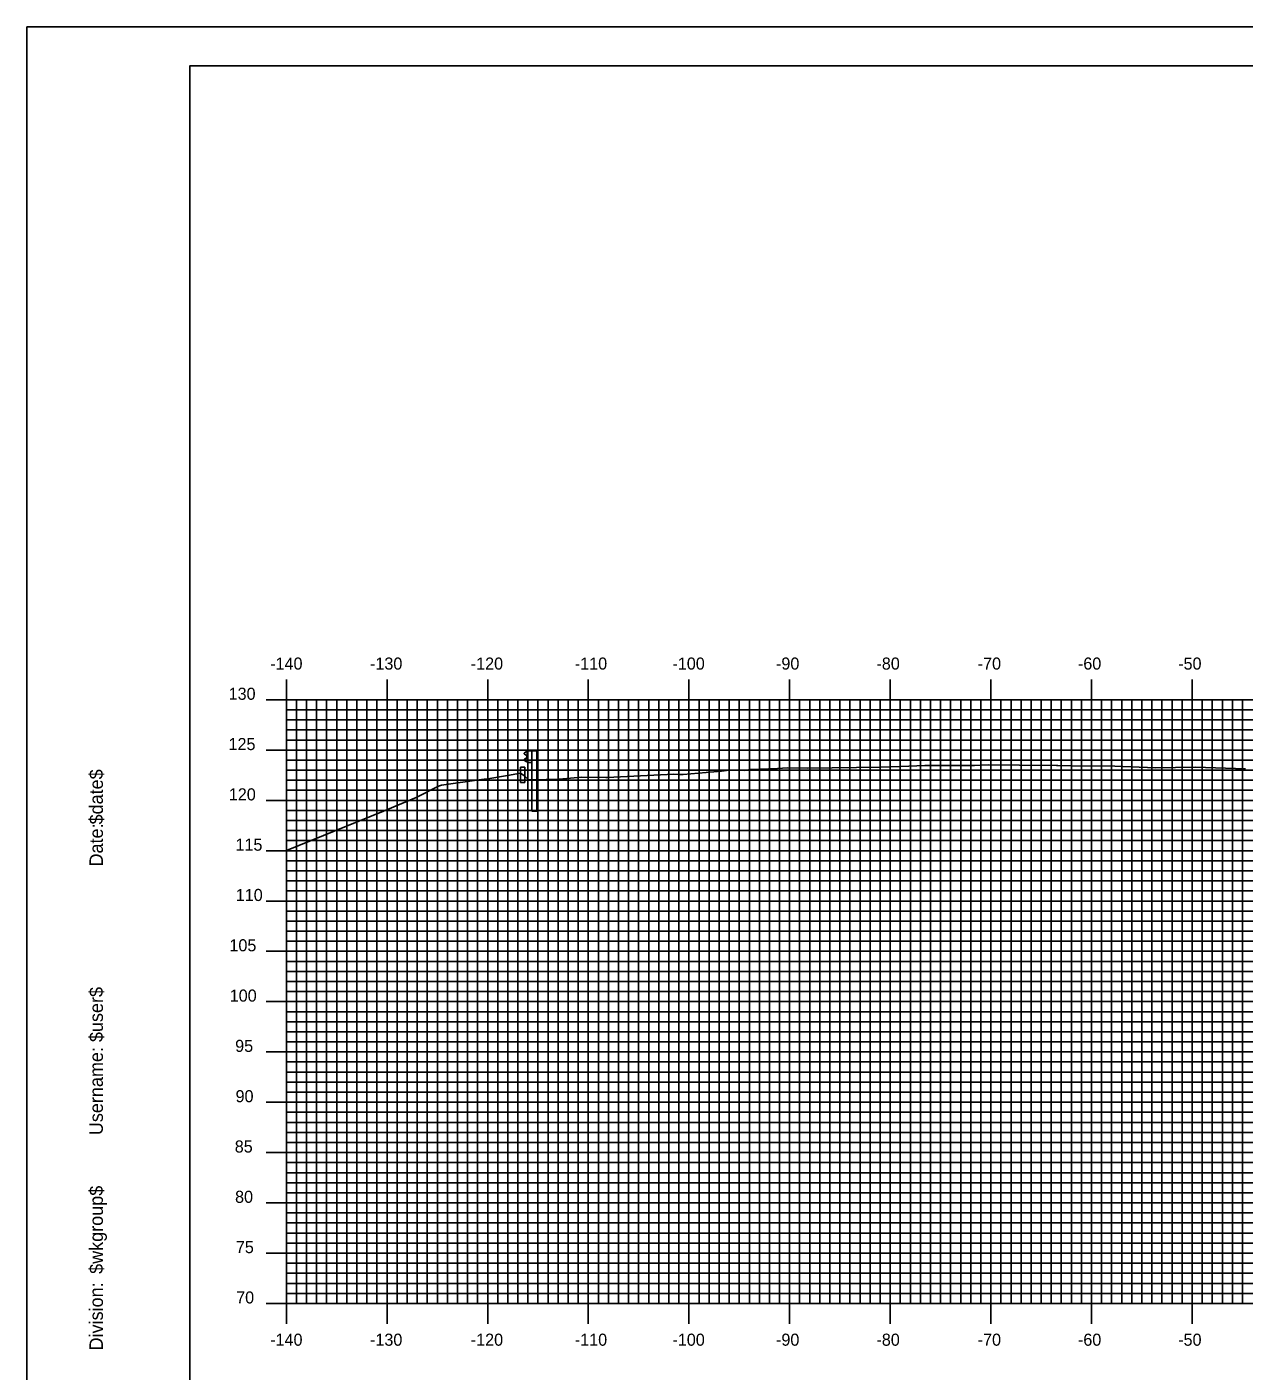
# Model space of a CAD drawing. Extents: x 856871 to 857214, y 364366 to 364586.
# Drawn here: x 856871 to 856992, y 364452.1 to 364585.7 of the extents above; entities that cross this region are included whole.
import ezdxf

# ---------------------------------------------------------------- set-up
doc = ezdxf.new("R2010")
doc.units = 0
for name, color, linetype in [('BORDER', 7, 'Continuous'), ('H_V ANNOTATION', 7, 'Continuous'), ('M_Roadway_Centerline', 7, 'Continuous'), ('MAJOR', 7, 'Continuous'), ('MINOR', 7, 'Continuous'), ('PLOT BOUNDARY', 7, 'Continuous'), ('S_Curb_Type_1', 7, 'Continuous'), ('S_Guardrail_Beam', 7, 'Continuous'), ('S_Roadway_Centerline', 7, 'Continuous')]:
    doc.layers.add(name, color=color, linetype=linetype)

msp = doc.modelspace()

# ---------------------------------------------------------------- linework, layer by layer
at = {"layer": 'BORDER'}
msp.add_lwpolyline([(856887.22, 364371.79), (857207.22, 364371.79), (857207.22, 364581.79), (856887.22, 364581.79)], close=True, dxfattribs=at)
at = {"layer": 'MAJOR'}
for p, q in [((856896.82, 364520.79), (856896.82, 364518.79)), ((856906.82, 364520.79), (856906.82, 364518.79)), ((856916.82, 364520.79), (856916.82, 364518.79)), ((856926.82, 364520.79), (856926.82, 364518.79)), ((856936.82, 364520.79), (856936.82, 364518.79)), ((856946.82, 364520.79), (856946.82, 364518.79)), ((856956.82, 364520.79), (856956.82, 364518.79)), ((856966.82, 364520.79), (856966.82, 364518.79)), ((856976.82, 364520.79), (856976.82, 364518.79)), ((856986.82, 364520.79), (856986.82, 364518.79)), ((856894.82, 364518.79), (856896.82, 364518.79)), ((856896.82, 364518.79), (857176.82, 364518.79)), ((856896.82, 364458.79), (856896.82, 364518.79)), ((856896.82, 364458.79), (856896.82, 364518.79)), ((856896.82, 364518.79), (857176.82, 364518.79)), ((856906.82, 364458.79), (856906.82, 364518.79)), ((856916.82, 364458.79), (856916.82, 364518.79)), ((856926.82, 364458.79), (856926.82, 364518.79)), ((856936.82, 364458.79), (856936.82, 364518.79)), ((856946.82, 364458.79), (856946.82, 364518.79)), ((856956.82, 364458.79), (856956.82, 364518.79)), ((856966.82, 364458.79), (856966.82, 364518.79)), ((856976.82, 364458.79), (856976.82, 364518.79)), ((856986.82, 364458.79), (856986.82, 364518.79)), ((856894.82, 364513.79), (856896.82, 364513.79)), ((856896.82, 364513.79), (857176.82, 364513.79)), ((856894.82, 364508.79), (856896.82, 364508.79)), ((856896.82, 364508.79), (857176.82, 364508.79)), ((856894.82, 364503.79), (856896.82, 364503.79)), ((856896.82, 364503.79), (857176.82, 364503.79)), ((856894.82, 364498.79), (856896.82, 364498.79)), ((856896.82, 364498.79), (857176.82, 364498.79)), ((856894.82, 364493.79), (856896.82, 364493.79)), ((856896.82, 364493.79), (857176.82, 364493.79)), ((856894.82, 364488.79), (856896.82, 364488.79)), ((856896.82, 364488.79), (857176.82, 364488.79)), ((856894.82, 364483.79), (856896.82, 364483.79)), ((856896.82, 364483.79), (857176.82, 364483.79)), ((856894.82, 364478.79), (856896.82, 364478.79)), ((856896.82, 364478.79), (857176.82, 364478.79)), ((856894.82, 364473.79), (856896.82, 364473.79)), ((856896.82, 364473.79), (857176.82, 364473.79)), ((856894.82, 364468.79), (856896.82, 364468.79)), ((856896.82, 364468.79), (857176.82, 364468.79)), ((856894.82, 364463.79), (856896.82, 364463.79)), ((856896.82, 364463.79), (857176.82, 364463.79)), ((856894.82, 364458.79), (856896.82, 364458.79)), ((856896.82, 364458.79), (857176.82, 364458.79)), ((856896.82, 364458.79), (857176.82, 364458.79)), ((856896.82, 364456.78), (856896.82, 364458.79)), ((856906.82, 364456.78), (856906.82, 364458.79)), ((856916.82, 364456.78), (856916.82, 364458.79)), ((856926.82, 364456.78), (856926.82, 364458.79)), ((856936.82, 364456.78), (856936.82, 364458.79)), ((856946.82, 364456.78), (856946.82, 364458.79)), ((856956.82, 364456.78), (856956.82, 364458.79)), ((856966.82, 364456.78), (856966.82, 364458.79)), ((856976.82, 364456.78), (856976.82, 364458.79)), ((856986.82, 364456.78), (856986.82, 364458.79))]:
    msp.add_line(p, q, dxfattribs=at)
at = {"layer": 'MINOR'}
for p, q in [((856897.82, 364458.79), (856897.82, 364518.79)), ((856898.82, 364458.79), (856898.82, 364518.79)), ((856899.82, 364458.79), (856899.82, 364518.79)), ((856900.82, 364458.79), (856900.82, 364518.79)), ((856901.82, 364458.79), (856901.82, 364518.79)), ((856902.82, 364458.79), (856902.82, 364518.79)), ((856903.82, 364458.79), (856903.82, 364518.79)), ((856904.82, 364458.79), (856904.82, 364518.79)), ((856905.82, 364458.79), (856905.82, 364518.79)), ((856907.82, 364458.79), (856907.82, 364518.79)), ((856908.82, 364458.79), (856908.82, 364518.79)), ((856909.82, 364458.79), (856909.82, 364518.79)), ((856910.82, 364458.79), (856910.82, 364518.79)), ((856911.82, 364458.79), (856911.82, 364518.79)), ((856912.82, 364458.79), (856912.82, 364518.79)), ((856913.82, 364458.79), (856913.82, 364518.79)), ((856914.82, 364458.79), (856914.82, 364518.79)), ((856915.82, 364458.79), (856915.82, 364518.79)), ((856917.82, 364458.79), (856917.82, 364518.79)), ((856918.82, 364458.79), (856918.82, 364518.79)), ((856919.82, 364458.79), (856919.82, 364518.79)), ((856920.82, 364458.79), (856920.82, 364518.79)), ((856921.82, 364458.79), (856921.82, 364518.79)), ((856922.82, 364458.79), (856922.82, 364518.79)), ((856923.82, 364458.79), (856923.82, 364518.79)), ((856924.82, 364458.79), (856924.82, 364518.79)), ((856925.82, 364458.79), (856925.82, 364518.79)), ((856927.82, 364458.79), (856927.82, 364518.79)), ((856928.82, 364458.79), (856928.82, 364518.79)), ((856929.82, 364458.79), (856929.82, 364518.79)), ((856930.82, 364458.79), (856930.82, 364518.79)), ((856931.82, 364458.79), (856931.82, 364518.79)), ((856932.82, 364458.79), (856932.82, 364518.79)), ((856933.82, 364458.79), (856933.82, 364518.79)), ((856934.82, 364458.79), (856934.82, 364518.79)), ((856935.82, 364458.79), (856935.82, 364518.79)), ((856937.82, 364458.79), (856937.82, 364518.79)), ((856938.82, 364458.79), (856938.82, 364518.79)), ((856939.82, 364458.79), (856939.82, 364518.79)), ((856940.82, 364458.79), (856940.82, 364518.79)), ((856941.82, 364458.79), (856941.82, 364518.79)), ((856942.82, 364458.79), (856942.82, 364518.79)), ((856943.82, 364458.79), (856943.82, 364518.79)), ((856944.82, 364458.79), (856944.82, 364518.79)), ((856945.82, 364458.79), (856945.82, 364518.79)), ((856947.82, 364458.79), (856947.82, 364518.79)), ((856948.82, 364458.79), (856948.82, 364518.79)), ((856949.82, 364458.79), (856949.82, 364518.79)), ((856950.82, 364458.79), (856950.82, 364518.79)), ((856951.82, 364458.79), (856951.82, 364518.79)), ((856952.82, 364458.79), (856952.82, 364518.79)), ((856953.82, 364458.79), (856953.82, 364518.79)), ((856954.82, 364458.79), (856954.82, 364518.79)), ((856955.82, 364458.79), (856955.82, 364518.79)), ((856957.82, 364458.79), (856957.82, 364518.79)), ((856958.82, 364458.79), (856958.82, 364518.79)), ((856959.82, 364458.79), (856959.82, 364518.79)), ((856960.82, 364458.79), (856960.82, 364518.79)), ((856961.82, 364458.79), (856961.82, 364518.79)), ((856962.82, 364458.79), (856962.82, 364518.79)), ((856963.82, 364458.79), (856963.82, 364518.79)), ((856964.82, 364458.79), (856964.82, 364518.79)), ((856965.82, 364458.79), (856965.82, 364518.79)), ((856967.82, 364458.79), (856967.82, 364518.79)), ((856968.82, 364458.79), (856968.82, 364518.79)), ((856969.82, 364458.79), (856969.82, 364518.79)), ((856970.82, 364458.79), (856970.82, 364518.79)), ((856971.82, 364458.79), (856971.82, 364518.79)), ((856972.82, 364458.79), (856972.82, 364518.79)), ((856973.82, 364458.79), (856973.82, 364518.79)), ((856974.82, 364458.79), (856974.82, 364518.79)), ((856975.82, 364458.79), (856975.82, 364518.79)), ((856977.82, 364458.79), (856977.82, 364518.79)), ((856978.82, 364458.79), (856978.82, 364518.79)), ((856979.82, 364458.79), (856979.82, 364518.79)), ((856980.82, 364458.79), (856980.82, 364518.79)), ((856981.82, 364458.79), (856981.82, 364518.79)), ((856982.82, 364458.79), (856982.82, 364518.79)), ((856983.82, 364458.79), (856983.82, 364518.79)), ((856984.82, 364458.79), (856984.82, 364518.79)), ((856985.82, 364458.79), (856985.82, 364518.79)), ((856987.82, 364458.79), (856987.82, 364518.79)), ((856988.82, 364458.79), (856988.82, 364518.79)), ((856989.82, 364458.79), (856989.82, 364518.79)), ((856990.82, 364458.79), (856990.82, 364518.79)), ((856991.82, 364458.79), (856991.82, 364518.79)), ((856896.82, 364517.79), (857176.82, 364517.79)), ((856896.82, 364517.79), (856898.83, 364517.79)), ((856896.82, 364516.79), (857176.82, 364516.79)), ((856896.82, 364516.79), (856898.83, 364516.79)), ((856896.82, 364515.79), (857176.82, 364515.79)), ((856896.82, 364515.79), (856898.83, 364515.79)), ((856896.82, 364514.79), (857176.82, 364514.79)), ((856896.82, 364514.79), (856898.83, 364514.79)), ((856896.82, 364512.79), (857176.82, 364512.79)), ((856896.82, 364512.79), (856898.83, 364512.79)), ((856896.82, 364511.79), (857176.82, 364511.79)), ((856896.82, 364511.79), (856898.83, 364511.79)), ((856896.82, 364510.79), (857176.82, 364510.79)), ((856896.82, 364510.79), (856898.83, 364510.79)), ((856896.82, 364509.79), (857176.82, 364509.79)), ((856896.82, 364509.79), (856898.83, 364509.79)), ((856896.82, 364507.79), (857176.82, 364507.79)), ((856896.82, 364507.79), (856898.83, 364507.79)), ((856896.82, 364506.79), (857176.82, 364506.79)), ((856896.82, 364506.79), (856898.83, 364506.79)), ((856896.82, 364505.79), (857176.82, 364505.79)), ((856896.82, 364505.79), (856898.83, 364505.79)), ((856896.82, 364504.79), (857176.82, 364504.79)), ((856896.82, 364504.79), (856898.83, 364504.79)), ((856896.82, 364502.79), (857176.82, 364502.79)), ((856896.82, 364502.79), (856898.83, 364502.79)), ((856896.82, 364501.79), (857176.82, 364501.79)), ((856896.82, 364501.79), (856898.83, 364501.79)), ((856896.82, 364500.79), (857176.82, 364500.79)), ((856896.82, 364500.79), (856898.83, 364500.79)), ((856896.82, 364499.79), (857176.82, 364499.79)), ((856896.82, 364499.79), (856898.83, 364499.79)), ((856896.82, 364497.79), (857176.82, 364497.79)), ((856896.82, 364497.79), (856898.83, 364497.79)), ((856896.82, 364496.79), (857176.82, 364496.79)), ((856896.82, 364496.79), (856898.83, 364496.79)), ((856896.82, 364495.79), (857176.82, 364495.79)), ((856896.82, 364495.79), (856898.83, 364495.79)), ((856896.82, 364494.79), (857176.82, 364494.79)), ((856896.82, 364494.79), (856898.83, 364494.79)), ((856896.82, 364492.79), (857176.82, 364492.79)), ((856896.82, 364492.79), (856898.83, 364492.79)), ((856896.82, 364491.79), (857176.82, 364491.79)), ((856896.82, 364491.79), (856898.83, 364491.79)), ((856896.82, 364490.79), (857176.82, 364490.79)), ((856896.82, 364490.79), (856898.83, 364490.79)), ((856896.82, 364489.79), (857176.82, 364489.79)), ((856896.82, 364489.79), (856898.83, 364489.79)), ((856896.82, 364487.79), (857176.82, 364487.79)), ((856896.82, 364487.79), (856898.83, 364487.79)), ((856896.82, 364486.79), (857176.82, 364486.79)), ((856896.82, 364486.79), (856898.83, 364486.79)), ((856896.82, 364485.79), (857176.82, 364485.79)), ((856896.82, 364485.79), (856898.83, 364485.79)), ((856896.82, 364484.79), (857176.82, 364484.79)), ((856896.82, 364484.79), (856898.83, 364484.79)), ((856896.82, 364482.79), (857176.82, 364482.79)), ((856896.82, 364482.79), (856898.83, 364482.79)), ((856896.82, 364481.79), (857176.82, 364481.79)), ((856896.82, 364481.79), (856898.83, 364481.79)), ((856896.82, 364480.79), (857176.82, 364480.79)), ((856896.82, 364480.79), (856898.83, 364480.79)), ((856896.82, 364479.79), (857176.82, 364479.79)), ((856896.82, 364479.79), (856898.83, 364479.79)), ((856896.82, 364477.79), (857176.82, 364477.79)), ((856896.82, 364477.79), (856898.83, 364477.79)), ((856896.82, 364476.79), (857176.82, 364476.79)), ((856896.82, 364476.79), (856898.83, 364476.79)), ((856896.82, 364475.79), (857176.82, 364475.79)), ((856896.82, 364475.79), (856898.83, 364475.79)), ((856896.82, 364474.79), (857176.82, 364474.79)), ((856896.82, 364474.79), (856898.83, 364474.79)), ((856896.82, 364472.79), (857176.82, 364472.79)), ((856896.82, 364472.79), (856898.83, 364472.79)), ((856896.82, 364471.79), (857176.82, 364471.79)), ((856896.82, 364471.79), (856898.83, 364471.79)), ((856896.82, 364470.79), (857176.82, 364470.79)), ((856896.82, 364470.79), (856898.83, 364470.79)), ((856896.82, 364469.79), (857176.82, 364469.79)), ((856896.82, 364469.79), (856898.83, 364469.79)), ((856896.82, 364467.79), (857176.82, 364467.79)), ((856896.82, 364467.79), (856898.83, 364467.79)), ((856896.82, 364466.79), (857176.82, 364466.79)), ((856896.82, 364466.79), (856898.83, 364466.79)), ((856896.82, 364465.79), (857176.82, 364465.79)), ((856896.82, 364465.79), (856898.83, 364465.79)), ((856896.82, 364464.79), (857176.82, 364464.79)), ((856896.82, 364464.79), (856898.83, 364464.79)), ((856896.82, 364462.79), (857176.82, 364462.79)), ((856896.82, 364462.79), (856898.83, 364462.79)), ((856896.82, 364461.79), (857176.82, 364461.79)), ((856896.82, 364461.79), (856898.83, 364461.79)), ((856896.82, 364460.79), (857176.82, 364460.79)), ((856896.82, 364460.79), (856898.83, 364460.79)), ((856896.82, 364459.79), (857176.82, 364459.79)), ((856896.82, 364459.79), (856898.83, 364459.79))]:
    msp.add_line(p, q, dxfattribs=at)
at = {"layer": 'PLOT BOUNDARY'}
msp.add_lwpolyline([(856871.04, 364365.67), (857211.04, 364365.67), (857211.04, 364585.67), (856871.04, 364585.67)], close=True, dxfattribs=at)
at = {"layer": 'S_Curb_Type_1'}
msp.add_lwpolyline([(856920.09, 364512.08), (856920.51, 364512.08), (856920.51, 364510.58), (856920.09, 364510.58)], close=True, dxfattribs=at)
msp.add_lwpolyline([(856920.09, 364512.08), (856920.51, 364512.08), (856920.51, 364510.58), (856920.09, 364510.58)], close=True, dxfattribs=at)
at = {"layer": 'S_Guardrail_Beam'}
for p, q in [((856920.63, 364513.62), (856920.49, 364513.52)), ((856920.63, 364513.62), (856920.49, 364513.52)), ((856920.49, 364513.38), (856920.68, 364513.24)), ((856920.49, 364513.38), (856920.68, 364513.24)), ((856920.73, 364513.64), (856920.65, 364513.63)), ((856920.73, 364513.64), (856920.65, 364513.63)), ((856920.73, 364513.72), (856921.22, 364513.72)), ((856920.73, 364512.55), (856920.73, 364513.72)), ((856920.73, 364513.72), (856921.22, 364513.72)), ((856920.73, 364512.55), (856920.73, 364513.72)), ((856921.22, 364513.72), (856921.71, 364513.72)), ((856921.22, 364513.72), (856921.22, 364512.55)), ((856921.22, 364513.72), (856921.71, 364513.72)), ((856921.22, 364513.72), (856921.22, 364512.55)), ((856921.71, 364513.72), (856921.71, 364507.72)), ((856921.71, 364513.72), (856921.71, 364507.72)), ((856920.68, 364513.02), (856920.49, 364512.89)), ((856920.68, 364513.02), (856920.49, 364512.89)), ((856920.49, 364512.74), (856920.63, 364512.64)), ((856920.49, 364512.74), (856920.63, 364512.64)), ((856920.65, 364512.64), (856920.73, 364512.62)), ((856920.65, 364512.64), (856920.73, 364512.62)), ((856920.72, 364513.18), (856920.72, 364513.09)), ((856920.72, 364513.18), (856920.72, 364513.09)), ((856921.22, 364512.55), (856920.73, 364512.55)), ((856921.22, 364512.55), (856920.73, 364512.55)), ((856921.22, 364507.72), (856921.22, 364512.55)), ((856921.22, 364507.72), (856921.22, 364512.55)), ((856921.22, 364507.72), (856921.71, 364507.72)), ((856921.22, 364507.72), (856921.71, 364507.72))]:
    msp.add_line(p, q, dxfattribs=at)
for centre, major_axis, start_param, end_param in [((856920.54, 364513.45), (-0.0877, 0), 5.323254, 7.243116), ((856920.54, 364513.45), (-0.0877, 0), 5.323254, 7.243116), ((856920.66, 364513.59), (-0.0417, 0), 4.886922, 5.323254), ((856920.66, 364513.59), (-0.0417, 0), 4.886922, 5.323254), ((856920.54, 364512.82), (-0.0877, 0), 5.323254, 7.243116), ((856920.54, 364512.82), (-0.0877, 0), 5.323254, 7.243116), ((856920.66, 364512.68), (-0.0417, 0), 0.959931, 1.396263), ((856920.66, 364512.68), (-0.0417, 0), 0.959931, 1.396263), ((856920.64, 364513.18), (0.0789, 0), 0, 0.959931), ((856920.64, 364513.18), (0.0789, 0), 0, 0.959931), ((856920.64, 364513.09), (0.0789, 0), 5.323254, 6.283185), ((856920.64, 364513.09), (0.0789, 0), 5.323254, 6.283185)]:
    msp.add_ellipse(centre, major_axis=major_axis, ratio=0.995501, start_param=start_param, end_param=end_param, dxfattribs=at)
at = {"layer": 'S_Roadway_Centerline'}
msp.add_lwpolyline([(856896.82, 364503.81), (856906.48, 364507.73), (856909.73, 364509.09), (856911.94, 364510.2), (856912.23, 364510.32), (856916.2, 364510.86), (856917.04, 364510.98), (856918.79, 364511.28), (856920.09, 364511.5), (856920.52, 364511.2), (856920.86, 364510.88), (856921.35, 364510.82), (856923.94, 364510.91), (856926.16, 364511.1), (856928.56, 364511.06), (856928.7, 364511.06), (856935.31, 364511.39), (856935.9, 364511.37), (856936.23, 364511.37), (856940.06, 364511.71), (856940.82, 364511.78), (856942.3, 364511.75), (856942.93, 364511.87), (856945.61, 364511.97), (856946.62, 364512.01), (856948.64, 364512), (856955.89, 364512.09), (856958.67, 364512.2), (856960.26, 364512.27), (856963.05, 364512.25), (856965.2, 364512.25), (856965.78, 364512.29), (856966.62, 364512.34), (856969.65, 364512.29), (856973.34, 364512.25), (856973.48, 364512.25), (856974.88, 364512.21), (856979.12, 364512.2), (856983.19, 364512.02), (856987.16, 364512.08), (856992.11, 364511.94)], dxfattribs=at)

# ---------------------------------------------------------------- texts
at = {"layer": 'BORDER'}
for s, p in [('$date$', (856878.59, 364506.4)), ('Date:', (856878.59, 364502.22)), ('$user$', (856878.59, 364484.77)), ('Username:', (856878.59, 364475.52)), ('$wkgroup$', (856878.59, 364461.73)), ('Division:', (856878.59, 364454.12))]:
    msp.add_text(s, height=1.339, rotation=90, dxfattribs=at).set_placement(p)
at = {"layer": 'H_V ANNOTATION'}
for s, p in [('-140', (856895.21, 364521.79)), ('-130', (856905.13, 364521.79)), ('-120', (856915.14, 364521.79)), ('-110', (856925.48, 364521.79)), ('-100', (856935.18, 364521.79)), ('-90', (856945.47, 364521.79)), ('-80', (856955.45, 364521.79)), ('-70', (856965.51, 364521.79)), ('-60', (856975.47, 364521.79)), ('-50', (856985.43, 364521.79)), ('130', (856891.08, 364518.79)), ('125', (856891.07, 364513.79)), ('120', (856891.1, 364508.79)), ('115', (856891.76, 364503.79)), ('110', (856891.79, 364498.79)), ('105', (856891.16, 364493.79)), ('100', (856891.19, 364488.79)), ('95', (856891.73, 364483.79)), ('90', (856891.77, 364478.79)), ('85', (856891.69, 364473.79)), ('80', (856891.72, 364468.79)), ('75', (856891.8, 364463.79)), ('70', (856891.83, 364458.79)), ('-140', (856895.21, 364454.59)), ('-130', (856905.13, 364454.59)), ('-120', (856915.14, 364454.59)), ('-110', (856925.48, 364454.59)), ('-100', (856935.18, 364454.59)), ('-90', (856945.47, 364454.59)), ('-80', (856955.45, 364454.59)), ('-70', (856965.51, 364454.59)), ('-60', (856975.47, 364454.59)), ('-50', (856985.43, 364454.59))]:
    msp.add_text(s, height=1.2, dxfattribs=at).set_placement(p)
at = {"layer": 'M_Roadway_Centerline'}
for s, p in [('C', (856965.78, 364512.29)), ('L', (856965.78, 364512.28)), ('C', (856935.31, 364511.39)), ('L', (856935.31, 364511.38))]:
    msp.add_text(s, height=0.0146, dxfattribs=at).set_placement(p)
at = {"layer": 'MAJOR'}
msp.add_text('-', height=0.012, dxfattribs=at).set_placement((856896.81, 364458.79))

doc.saveas('drawing.dxf')
